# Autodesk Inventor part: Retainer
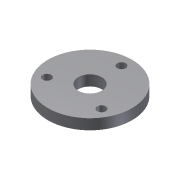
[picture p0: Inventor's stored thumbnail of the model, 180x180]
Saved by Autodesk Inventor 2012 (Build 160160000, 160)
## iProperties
Created: 2009-04
Part Number: Retainer
Document SubType Name: Modeling
Designer: Sham
Density: 1 g/cm^3
Material: Default
Mass: 699.549 g
Surface Area: 808.532 cm^2
Volume: 699.549 cm^3
Author: Sham
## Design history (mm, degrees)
sketch "Sketch1"
  geometry: C1 r 100 at (0, 0); C2 r 28 at (0, 0)
  constraints: 2 centre point, 1 coincident
  dimensions: "d0" = 200 diameter of C1; "d1" = 56 diameter of C2
extrude "Extrusion2" new body sketch "Sketch1" distance "d10" = 25; taper "d11" = 0 deg
sketch "Sketch2"
  geometry: C1 r 28 at (0, 0) reference; 1 further point
  constraints: 1 vertical alignment
  dimensions: "d12" = 75 distance of C1.centre point (0, 75)
hole "Hole1" sketch "Sketch2" at (0, 75) diameter "d13" = 20.3; stored, may be unused: countersink angle "d17" = 90 deg, drill point angle "d19" = 118 deg; dims "d14" = 6, "d15" = 4, "d16" = 2, "d18" = 8
pattern_circular "Circular Pattern1" dims angle "d21" = 360 deg
body "Solid2"
